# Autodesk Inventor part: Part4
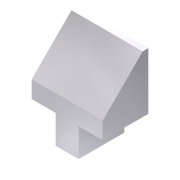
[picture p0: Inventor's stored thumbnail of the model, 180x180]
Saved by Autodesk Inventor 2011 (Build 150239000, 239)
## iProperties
Shininess: 77.0
Length Units: 11269
Angle Units: 11279
Time Units: 11290
Mass Units: 11283
Length Display Precision: 3
Angle Display Precision: 2
Created: 2002-01
Part Number: Part4
Document SubType Name: Modeling
Designer: ***
Density: 1 g/cm^3
Density: 0.0
Volumn: 0.0
Area: 0.0
PropertySet Name: Model Information
Control State: 0
Master: False
Checked Out: False
Author: ***
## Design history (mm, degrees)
sketch "Sketch2"
  geometry: L1 (2.32, -6.969)-(2.32, 13.031); L2 (2.32, 13.031)-(0.32, 13.031); L3 (0.32, 13.031)-(-13.68, -0.969); L4 (-13.68, -0.969)-(-13.68, -6.969); L5 (-13.68, -6.969)-(2.32, -6.969)
  constraints: 10 end point, 2 parallel, 1 perpendicular, 1 vertical
  dimensions: "d0" = 2 distance of L1.end L2.end; "d1" = 135 deg angle of L4 L3; "d2" = 20 distance of L1.start L1.end; "d3" = 16 distance of L4.end L1.start
extrude "Extrusion1" new body sketch "Sketch2" stored distance "d4" = 25; taper "d5" = 0 deg
sketch "Sketch3"
  geometry: L1 (-13.68, -6.969)-(2.32, -6.969); L2 (2.32, -6.969)-(2.32, -16.969); L3 (2.32, -16.969)-(-13.68, -16.969); L4 (-13.68, -16.969)-(-13.68, -6.969); L5 (-13.68, -6.969)-(2.32, -6.969) reference; L6 (-13.68, -0.969)-(-13.68, -6.969) reference; L7 (2.32, -6.969)-(2.32, 13.031) reference
  constraints: 8 end point, 3 collinear, 2 parallel, 1 horizontal, 1 perpendicular
  dimensions: "d6" = 10 distance of L3.end L1.start
extrude "Extrusion2" join sketch "Sketch3" stored distance "d7" = 8; taper "d8" = 0 deg
body "Solid1"
